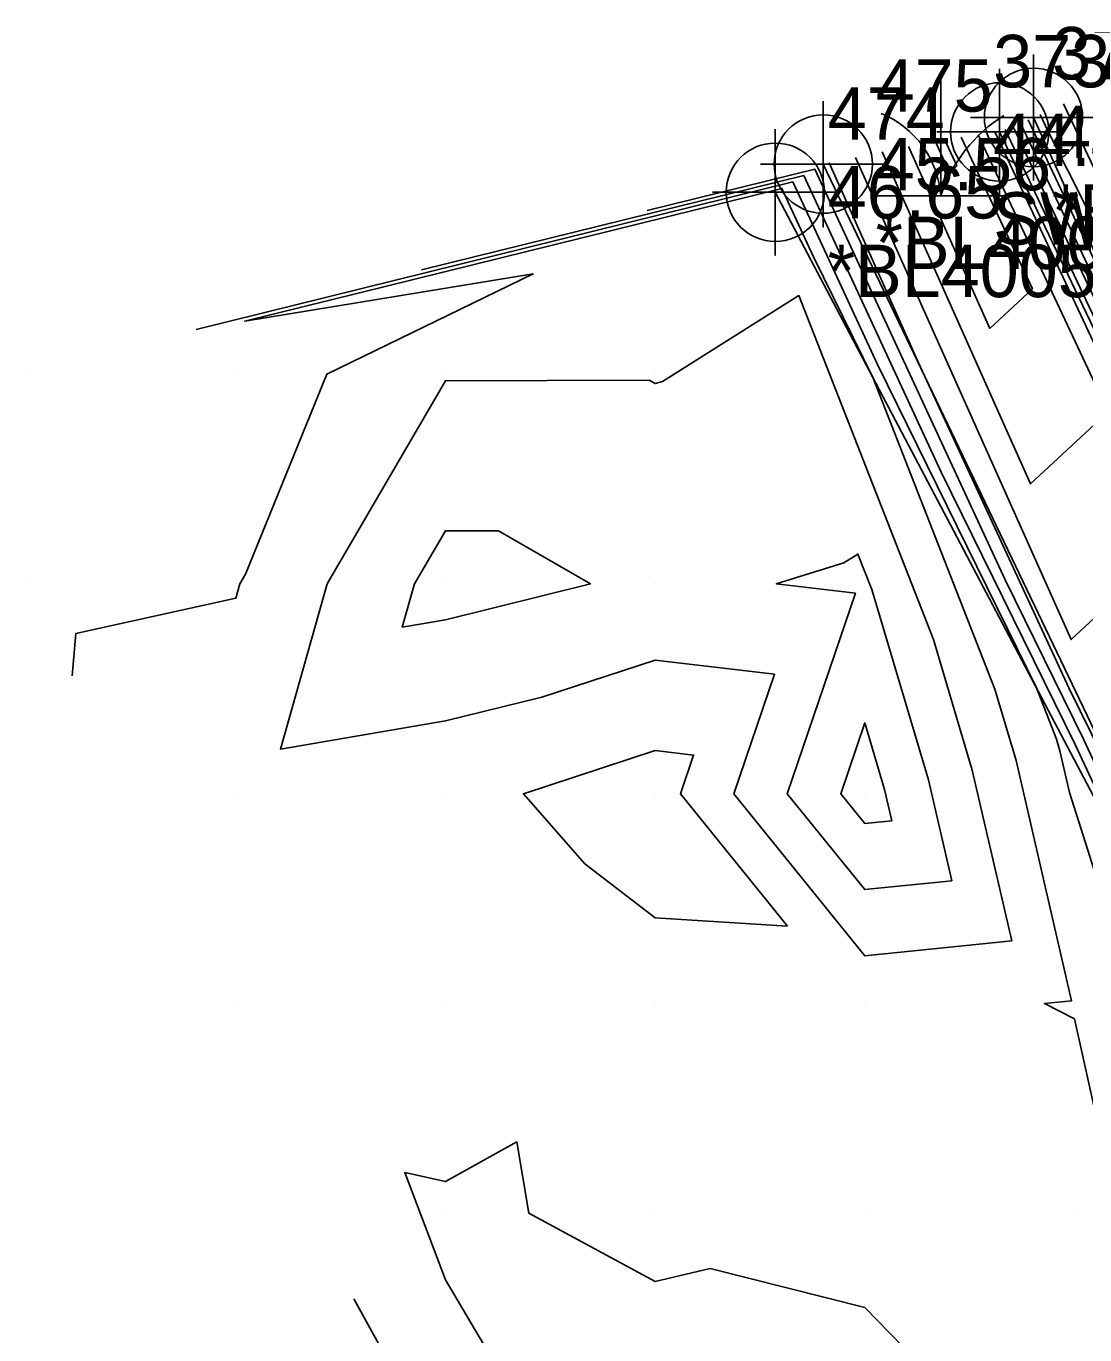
# Model space of a CAD drawing. Extents: x 2090860 to 2091277, y 159470 to 160080.
# Drawn here: x 2090860 to 2090910.5, y 159984.2 to 160046.6 of the extents above; entities that cross this region are included whole.
import ezdxf

# ---------------------------------------------------------------- set-up
doc = ezdxf.new("R2010")
doc.units = 0
for name, color, linetype in [('DTM Contours Major', 7, 'Continuous'), ('DTM Contours Minor', 7, 'Continuous'), ('Exist DTM Breakline', 7, 'Continuous'), ('Exist DTM Breakline Cogo Comment', 7, 'Continuous'), ('Exist DTM Breakline Cogo Elevation', 7, 'Continuous'), ('Exist DTM Breakline Cogo Number', 7, 'Continuous'), ('Exist DTM Breakline Cogo Point CELL', 7, 'Continuous'), ('Exist DTM QL2 LIDAR Elevation Point', 7, 'Continuous'), ('Exist Hydro Swamp or Marsh', 7, 'Continuous'), ('Exist Hydro Swamp or Marsh Cogo Comment', 7, 'Continuous'), ('Exist Hydro Swamp or Marsh Cogo Elevation', 7, 'Continuous'), ('Exist Hydro Swamp or Marsh Cogo Number', 7, 'Continuous')]:
    doc.layers.add(name, color=color, linetype=linetype)

msp = doc.modelspace()

# ---------------------------------------------------------------- linework, layer by layer
at = {"layer": 'DTM Contours Major'}
for points in [[(2090900.828, 160040.593), (2090907.904, 160024.765), (2090911.605, 160028.202), (2090905.415, 160041.412)], [(2090907.426, 160041.969), (2090911.786, 160032.768), (2090917.984, 160019.602), (2090928.464, 159997.339), (2090930.876, 159992.521), (2090937.332, 159979.157), (2090937.542, 159978.71), (2090949.879, 159953.162), (2090950.574, 159951.679), (2090954.727, 159942.562), (2090954.886, 159942.222), (2090962.638, 159925.196), (2090966.571, 159916.855), (2090967.464, 159914.985), (2090973.015, 159903.605)], [(2090878.864, 160034.967), (2090897.091, 160039.466), (2090903.651, 160025.321), (2090910.038, 160012.34), (2090912.377, 160007.335), (2090915.967, 160000.292), (2090918.562, 159992.105), (2090919.202, 159989.241), (2090921.362, 159986.426), (2090931.819, 159965.183), (2090930.712, 159963.948), (2090932.018, 159960.802), (2090932.724, 159957.106), (2090937.257, 159949.444), (2090930, 159941.72), (2090927.457, 159942.543), (2090920, 159946.378), (2090916.149, 159943.851), (2090910, 159943.546), (2090902.359, 159947.641), (2090900, 159946.671), (2090893.58, 159946.42), (2090892.56, 159944.88)], [(2090878.527, 160020), (2090880, 160022.531), (2090882.537, 160022.537), (2090886.912, 160020), (2090880, 160018.293), (2090877.943, 160017.943), (2090878.527, 160020)], [(2090900.339, 160019.726), (2090899.675, 160021.424), (2090899, 160021), (2090895.775, 160020), (2090899.554, 160019.554), (2090896.306, 160010), (2090900, 160005.429), (2090904.148, 160005.852), (2090903.034, 160010.666), (2090900.339, 160019.726)]]:
    msp.add_lwpolyline(points, dxfattribs=at)
at = {"layer": 'DTM Contours Minor'}
for points in [[(2090909.485, 160042.884), (2090911.08, 160039.501), (2090920.496, 160020.825), (2090923.543, 160014.354), (2090933.768, 159993.933), (2090938.255, 159984.643), (2090940.449, 159979.964), (2090949.023, 159962.207), (2090953.39, 159952.892), (2090956.276, 159946.558), (2090957.734, 159943.424), (2090966.547, 159924.07), (2090970.225, 159916.166), (2090974.377, 159907.749), (2090976.119, 159903.975)], [(2090907.788, 160042.123), (2090909.613, 160038.271), (2090916.596, 160023.437), (2090918.424, 160019.813), (2090918.625, 160019.385), (2090931.84, 159992.992), (2090937.64, 159980.985), (2090938.511, 159979.128), (2090949.594, 159956.177), (2090951.513, 159952.083), (2090955.244, 159943.894), (2090955.835, 159942.622), (2090967.245, 159917.565), (2090968.277, 159915.347), (2090973.673, 159904.407)], [(2090908.363, 160042.375), (2090908.712, 160041.635), (2090919.46, 160020.319), (2090921.084, 160016.87), (2090932.804, 159993.462), (2090937.948, 159982.814), (2090939.48, 159979.546), (2090949.308, 159959.192), (2090952.452, 159952.487), (2090955.76, 159945.226), (2090956.784, 159943.023), (2090966.896, 159920.817), (2090969.251, 159915.756), (2090974.025, 159906.078), (2090975.157, 159903.624)], [(2090899.563, 160040.331), (2090909.838, 160017.348), (2090915.213, 160022.339), (2090906.225, 160041.521)], [(2090906.701, 160041.663), (2090916.132, 160021.763), (2090917.301, 160019.278), (2090919.911, 160013.734), (2090930.148, 159992.169), (2090935.256, 159981.379), (2090936.616, 159978.521), (2090944.254, 159962.401), (2090949.505, 159951.363), (2090952.287, 159945.521), (2090954.079, 159941.72), (2090957.972, 159933.464), (2090966.981, 159914.593), (2090968.004, 159912.496), (2090972.898, 159902.775)], [(2090907.064, 160041.816), (2090913.959, 160027.266), (2090917.643, 160019.44), (2090925.862, 160001.979), (2090930.45, 159992.315), (2090932.739, 159987.48), (2090936.984, 159978.555), (2090940.085, 159972.01), (2090949.879, 159951.423), (2090950.719, 159949.661), (2090954.36, 159941.937), (2090962.272, 159925.16), (2090967.223, 159914.789), (2090970.51, 159908.05), (2090973.119, 159902.868)], [(2090902.092, 160040.854), (2090905.969, 160032.182), (2090907.998, 160034.065), (2090904.606, 160041.303)], [(2090903.357, 160041.116), (2090904.035, 160039.599), (2090904.39, 160039.928), (2090903.797, 160041.194)], [(2090889.626, 160037.801), (2090897.613, 160039.773), (2090906.696, 160020.187), (2090910.431, 160012.597), (2090915.684, 160001.354), (2090921.934, 159989.091), (2090923.078, 159986.602), (2090934.563, 159961.929)], [(2090898.298, 160040.07), (2090902.561, 160030.534), (2090909.741, 160015.052), (2090910.823, 160012.853), (2090918.991, 159995.373), (2090922.033, 159989.405), (2090928.025, 159976.37), (2090934.637, 159962.164), (2090937.707, 159955.499), (2090940.625, 159949.227), (2090948.523, 159931.794), (2090953.056, 159921.956), (2090965.045, 159895.337)], [(2090868.102, 160032.133), (2090896.569, 160039.16), (2090900.606, 160030.455), (2090908.186, 160015.051), (2090909.143, 160012.603), (2090909.31, 160012.043), (2090909.771, 160010.051), (2090914.18, 159996.146), (2090915.655, 159989.533), (2090920.643, 159983.036), (2090925.583, 159973.001), (2090921.92, 159968.915), (2090922.513, 159967.487), (2090920, 159968.451), (2090915.329, 159970), (2090910, 159971.335), (2090905.305, 159974.695), (2090900, 159975.694), (2090891.754, 159970), (2090890, 159969.104), (2090886.285, 159967.429), (2090886.339, 159960.983), (2090883.674, 159965.814)], [(2090918.502, 159981.498), (2090912.109, 159989.826), (2090910, 159999.276), (2090908.566, 160000), (2090909.867, 160000.133), (2090907.218, 160011.584), (2090906.209, 160014.977), (2090900.403, 160029.812), (2090897.561, 160035.589), (2090896.047, 160038.853), (2090870.427, 160032.529), (2090884.177, 160034.776), (2090874.349, 160030), (2090870.467, 160020.467), (2090870.195, 160020), (2090870, 160019.313), (2090862.368, 160017.632), (2090862.193, 160015.615)], [(2090903.274, 160017.351), (2090896.86, 160033.742), (2090890.346, 160029.654), (2090890, 160029.546), (2090889.713, 160029.713), (2090880, 160029.688), (2090874.361, 160020), (2090872.127, 160012.127), (2090880, 160013.467), (2090884.604, 160014.604), (2090890, 160016.368), (2090895.695, 160015.695), (2090893.759, 160010), (2090900, 160002.278), (2090907.008, 160002.992), (2090905.126, 160011.125), (2090903.274, 160017.351)], [(2090900.942, 160010.207), (2090900, 160013.374), (2090898.853, 160010), (2090900, 160008.581), (2090901.288, 160008.712), (2090900.942, 160010.207)], [(2090896.32, 160003.68), (2090891.212, 160010), (2090891.837, 160011.837), (2090890, 160012.053), (2090883.717, 160010), (2090886.654, 160006.654), (2090890, 160004.08), (2090896.32, 160003.68)], [(2090884.048, 159980), (2090880, 159986.822), (2090878.059, 159991.941), (2090880, 159991.513), (2090883.398, 159993.398), (2090883.974, 159990), (2090890, 159986.755), (2090892.627, 159987.373), (2090900, 159985.502), (2090905.379, 159980)], [(2090875.634, 159985.914), (2090881.686, 159974.941)]]:
    msp.add_lwpolyline(points, dxfattribs=at)
at = {"layer": 'Exist DTM Breakline'}
for points in [[(2091019.809, 159801.913), (2091004.418, 159836.946), (2090986.475, 159875.987), (2090967.517, 159915.028), (2090950.041, 159951.449), (2090930.695, 159992.433), (2090908.049, 160042.233)], [(2091019.111, 159801.55), (2091003.076, 159836.513), (2090986.016, 159875.809), (2090966.872, 159914.505), (2090949.073, 159951.294), (2090930.109, 159992.15), (2090906.432, 160041.549)], [(2090898.02, 160040.012), (2090922.126, 159989.703), (2090940.871, 159949.246), (2090967.299, 159891.857)], [(2090895.734, 160038.669), (2090921.911, 159989.017), (2090940.353, 159949.207), (2090966.689, 159891.716)]]:
    msp.add_lwpolyline(points, dxfattribs=at)
at = {"layer": 'Exist DTM Breakline Cogo Point CELL'}
for points in [[(2090908.049, 160045.233), (2090908.049, 160039.233), (2090908.049, 160042.233), (2090911.049, 160042.233), (2090905.049, 160042.233)], [(2090906.432, 160044.549), (2090906.432, 160038.549), (2090906.432, 160041.549), (2090909.432, 160041.549), (2090903.432, 160041.549)], [(2090898.02, 160043.012), (2090898.02, 160037.012), (2090898.02, 160040.012), (2090901.02, 160040.012), (2090895.02, 160040.012)], [(2090895.734, 160041.669), (2090895.734, 160035.669), (2090895.734, 160038.669), (2090898.734, 160038.669), (2090892.734, 160038.669)]]:
    msp.add_lwpolyline(points, dxfattribs=at)
for centre in [(2090908.049, 160042.233), (2090906.432, 160041.549), (2090898.02, 160040.012), (2090895.734, 160038.669)]:
    msp.add_circle(centre, 2.344, dxfattribs=at)
at = {"layer": 'Exist DTM QL2 LIDAR Elevation Point'}
for p, q in [((2090860, 160030), (2090860, 160030)), ((2090870, 160030), (2090870, 160030)), ((2090880, 160030), (2090880, 160030)), ((2090890, 160030), (2090890, 160030)), ((2090860, 160020), (2090860, 160020)), ((2090870, 160020), (2090870, 160020)), ((2090880, 160020), (2090880, 160020)), ((2090890, 160020), (2090890, 160020)), ((2090900, 160020), (2090900, 160020)), ((2090870, 160010), (2090870, 160010)), ((2090880, 160010), (2090880, 160010)), ((2090890, 160010), (2090890, 160010)), ((2090900, 160010), (2090900, 160010)), ((2090870, 160000), (2090870, 160000)), ((2090880, 160000), (2090880, 160000)), ((2090890, 160000), (2090890, 160000)), ((2090900, 160000), (2090900, 160000)), ((2090910, 160000), (2090910, 160000)), ((2090880, 159990), (2090880, 159990)), ((2090890, 159990), (2090890, 159990)), ((2090900, 159990), (2090900, 159990)), ((2090910, 159990), (2090910, 159990))]:
    msp.add_line(p, q, dxfattribs=at)
at = {"layer": 'Exist Hydro Swamp or Marsh'}
msp.add_line((2090903.625, 160041.171), (2090903.625, 160041.171), dxfattribs=at)
msp.add_lwpolyline([(2090900.4, 160038.497), (2090903.626, 160038.497), (2090903.626, 160044.414), (2090903.626, 160038.497), (2090906.851, 160038.497)], dxfattribs=at)
for centre, radius, start, end in [((2090899.026, 160038.164), 4.612, 4.14034, 67.53497), ((2090910.467, 160036.224), 7.208, 122.12745, 161.62219)]:
    msp.add_arc(centre, radius, start, end, dxfattribs=at)

# ---------------------------------------------------------------- texts
at = {"layer": 'Exist DTM Breakline Cogo Comment'}
for s, p in [('*EL40052', (2090908.932, 160036.549)), ('*BL40053', (2090900.52, 160035.012)), ('*BL40054', (2090898.234, 160033.669))]:
    msp.add_text(s, height=2.5, dxfattribs=at).set_placement(p)
at = {"layer": 'Exist DTM Breakline Cogo Elevation'}
for s, p in [('45.31', (2090908.932, 160040.299)), ('45.56', (2090900.52, 160038.762)), ('46.65', (2090898.234, 160037.419))]:
    msp.add_text(s, height=2.5, dxfattribs=at).set_placement(p)
at = {"layer": 'Exist DTM Breakline Cogo Number'}
for s, p in [('372', (2090908.932, 160044.049)), ('475', (2090900.52, 160042.512)), ('474', (2090898.234, 160041.169))]:
    msp.add_text(s, height=2.5, dxfattribs=at).set_placement(p)
at = {"layer": 'Exist Hydro Swamp or Marsh Cogo Comment'}
msp.add_text('SWAMP AREA', height=2.5, dxfattribs=at).set_placement((2090906.125, 160036.171))
at = {"layer": 'Exist Hydro Swamp or Marsh Cogo Elevation'}
msp.add_text('44.45', height=2.5, dxfattribs=at).set_placement((2090906.125, 160039.921))
at = {"layer": 'Exist Hydro Swamp or Marsh Cogo Number'}
msp.add_text('373', height=2.5, dxfattribs=at).set_placement((2090906.125, 160043.671))

doc.saveas('drawing.dxf')
